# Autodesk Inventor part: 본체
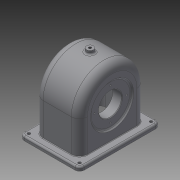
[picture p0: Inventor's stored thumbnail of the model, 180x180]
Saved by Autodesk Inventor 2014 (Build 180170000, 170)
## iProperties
Created: 2016-01
Part Number: 본체
Material: 일반
Document SubType Name: Modeling
Designer: basic
Density: 1 g/cm^3
Appearance: 기본값
Author: basic
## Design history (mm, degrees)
sketch "스케치1"
  geometry: L1 (-52, 70)-(52, 70); L2 (52, 70)-(52, -70); L3 (52, -70)-(-52, -70); L4 (-52, -70)-(-52, 70); 3 further points
  constraints: 8 end point, 2 midpoint, 2 parallel, 1 horizontal, 1 horizontal alignment, 1 perpendicular, 1 vertical alignment
  dimensions: "d0" = 104 distance of L1.start L1.end; "d1" = 140 distance of L1.end L2.end
extrude "돌출1" new body sketch "스케치1" distance "d2" = 7; taper "d3" = 0 deg
sketch "스케치2"
  geometry: L1 (-57, 7)-(-57, 64); L2 (57, 64)-(57, 7); L3 (70, 0)-(-70, 0) reference; L4 (70, 7)-(-70, 7) reference; L5 (-50.604, 7)-(57, 7); A1 r 57 centre (0, 64) between (57, 64) and (-57, 64); 2 further points
  constraints: 6 end point, 3 point on line, 2 point on circle, 2 tangent, 1 centre point, 1 collinear, 1 midpoint, 1 parallel, 1 vertical, 1 vertical alignment
  dimensions: "d4" = 64 distance from line of L3 A1.centre; "d5" = 57 radius of A1
extrude "돌출2" join sketch "스케치2" stored distance "d6" = 77; taper "d7" = 0 deg
sketch "스케치3"
  geometry: L1 (-38.5, 103.943)-(-19.5, 88); L2 (-19.5, 88)-(-19.5, 60); L3 (-19.5, 60)-(-38.5, 60); L4 (-38.5, 60)-(-38.5, 103.943); L5 (38.5, 64)-(-38.5, 64) reference; L6 (-38.5, 64)-(-38.5, 64) reference; L7 (38.5, 64)-(-38.5, 64) reference; L8 (38.5, 64)-(38.5, 64) reference; L9 (-38.5, 121)-(-38.5, 64) reference; L10 (-38.5, 64)-(-38.5, 7) reference; L11 (38.5, 64)-(38.5, 121) reference; L12 (38.5, 7)-(38.5, 64) reference; L13 (-52, 0)-(52, 0) reference; L14 (38.5, 91)-(48.5, 91); L15 (48.5, 91)-(48.5, 60); L16 (48.5, 60)-(38.5, 60); L17 (38.5, 60)-(38.5, 91); 2 further points
  constraints: 16 end point, 3 parallel, 2 collinear, 2 perpendicular, 1 horizontal, 1 midpoint, 1 point on line, 1 vertical
  dimensions: "d8" = 60 distance between parallel lines of L13 L3; "d9" = 19 distance between parallel lines of L2 L4; "d10" = 50 deg angle of L2 L1; "d11" = 56 diameter of L1.end L3; "d12" = 10 distance between parallel lines of L17 L15; "d13" = 62 diameter of L14 L16
  node "투영된 루프1"
sketch "스케치4"
  geometry: L1 (-57, 7)-(-57, 64) reference; L2 (57, 64)-(57, 7) reference; L3 (-51, 0)-(-51, 64); L4 (51, 64)-(51, 0); L5 (-70, 0)-(70, 0) reference; A1 r 57 centre (0, 64) between (57, 64) and (-57, 64) reference; A2 r 51 centre (0, 64) between (51, 64) and (-51, 64); 1 further point
  constraints: 4 end point, 2 point on circle, 2 point on line, 1 centre point, 2 other
  dimensions: "d14" = 6 distance between parallel lines of L2 L4
extrude "돌출3" cut sketch "스케치4" stored distance "d15" = 67; taper "d16" = 0 deg
revolve "회전1" stored, may be unused: angle "d17" = 90 deg
fillet "모깎기1" dims "d18" = 8
hole "구멍1" diameter "d21" = 5; stored, may be unused: countersink angle "d25" = 90 deg, drill point angle "d27" = 118 deg; dims "d19" = 10, "d20" = 10, "d22" = 6, "d23" = 4, "d24" = 2, "d26" = 8
hole "구멍2" diameter "d30" = 5; stored, may be unused: countersink angle "d34" = 90 deg, drill point angle "d36" = 118 deg; dims "d28" = 10, "d29" = 10, "d31" = 6, "d32" = 4, "d33" = 2, "d35" = 8
hole "구멍3" diameter "d39" = 5; stored, may be unused: countersink angle "d43" = 90 deg, drill point angle "d45" = 118 deg; dims "d37" = 10, "d38" = 10, "d40" = 6, "d41" = 4, "d42" = 2, "d44" = 8
hole "구멍4" diameter "d48" = 5; stored, may be unused: countersink angle "d52" = 90 deg, drill point angle "d54" = 118 deg; dims "d46" = 10, "d47" = 10, "d49" = 6, "d50" = 4, "d51" = 2, "d53" = 8
fillet "모깎기2" dims "d55" = 3
fillet "모깎기3" dims "d56" = 14, "d57" = 9
node "작업 평면1"
sketch "스케치5"
  geometry: C1 r 6 at (0, 0); 1 further point
  constraints: 1 centre point, 1 coincident
  dimensions: "d59" = 12 diameter of C1
extrude "돌출4" join sketch "스케치5" stored distance "d60" = 67; taper "d61" = 0 deg
fillet "모깎기4" dims "d62" = 3
hole "구멍5" diameter "d65" = 4.459; stored, may be unused: countersink angle "d69" = 90 deg, drill point angle "d71" = 118 deg; dims "d63" = 10, "d64" = 10, "d66" = 6, "d67" = 4, "d68" = 2, "d70" = 30
sketch "스케치6"
  geometry: L1 (-38.5, 64)-(-38.5, 107) reference; L2 (-19.5, 32)-(-19.5, 88) reference; L3 (-19.5, 60)-(-38.5, 60); L4 (-38.5, 60)-(-38.5, 97.416); L5 (-38.5, 97.416)-(-35.5, 94.899); L6 (-19.5, 80)-(-19.5, 60); L7 (-33.5, 99.747)-(-19.5, 88) reference; L8 (-33.5, 64)-(-24.5, 64) reference; L9 (-24.5, 64)-(-24.5, 64) reference; L10 (-33.5, 64)-(-24.5, 64) reference; L11 (-33.5, 64)-(-33.5, 64) reference; L12 (-35.5, 80)-(-35.5, 94.899); L13 (-19.5, 80)-(-35.5, 80); 1 further point
  constraints: 12 end point, 2 collinear, 2 parallel, 2 perpendicular, 1 midpoint, 1 point on line, 1 vertical
  dimensions: "d74" = 5 distance between parallel lines of L5 L7; "d75" = 3 distance between parallel lines of L12 L1; "d76" = 40 diameter of L13 L3
revolve "회전2" sketch "스케치6" stored, may be unused: angle "d77" = 90 deg
fillet "모깎기5" dims "d78" = 3
chamfer "모따기1" distance "d79" = 1; stored, may be unused: second distance "d80" = 2, angle "d81" = 45 deg
hole "구멍6" diameter "d84" = 40; stored, may be unused: countersink angle "d88" = 90 deg, drill point angle "d90" = 118 deg; dims "d82" = 10, "d83" = 10, "d85" = 6, "d86" = 4, "d87" = 2, "d89" = 4
chamfer "모따기2" distance "d91" = 1; stored, may be unused: second distance "d92" = 2, angle "d93" = 45 deg
fillet "모깎기6" dims "d94" = 1, "d95" = 3
sketch "스케치7"
  geometry: L1 (60, -42)-(60, 42) reference; C1 r 33.5 at (0, 0) reference; 3 further points
  constraints: 1 coincident, 1 midpoint
  dimensions: "d96" = 28 distance of point (-28, 0) C1.centre
hole "구멍7" sketch "스케치7" at (-28, 0) diameter "d97" = 2.459; stored, may be unused: countersink angle "d101" = 90 deg, drill point angle "d103" = 118 deg; dims "d98" = 7, "d99" = 4, "d100" = 2, "d102" = 9
sketch "스케치8"
  geometry: C1 r 31 at (0, 0) reference; 2 further points
  constraints: 1 horizontal alignment
  dimensions: "d107" = 24 distance of C1.centre point (24, 0)
hole "구멍8" sketch "스케치8" at (24, 0) diameter "d108" = 2.459; stored, may be unused: countersink angle "d112" = 90 deg, drill point angle "d114" = 118 deg; dims "d109" = 6, "d110" = 4, "d111" = 2, "d113" = 8
sketch "스케치9"
  geometry: L1 (-19.5, 64)-(68.5, 64) reference; L2 (76.5, 60)-(76.5, 64) reference; L3 (63, 0)-(63, 56) reference; 2 further points
  constraints: 1 other
  dimensions: "d118" = 30 distance from line of L1 point (24.5, 34); "d120" = 38.5 distance from line of L3 point (24.5, 34)
feature "엠보싱1" sketch "스케치9" dims "d0" = 104, "d1" = 140, "d8" = 60, "d9" = 19, "d10" = 50 deg, "d11" = 56, "d12" = 10, "d13" = 62, "d121" = 0.5, "d122" = 0
node "솔리드1"
pattern_circular "원형 패턴1" dims angle "d105" = 360 deg
pattern_circular "원형 패턴2" dims angle "d116" = 360 deg
node "투영된 루프2"
other parameters: "d58" = 127
